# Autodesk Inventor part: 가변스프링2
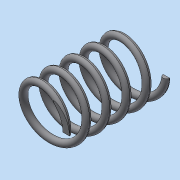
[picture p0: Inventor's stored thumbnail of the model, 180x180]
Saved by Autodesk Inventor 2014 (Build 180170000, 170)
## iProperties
Created: 2018-10
Part Number: 가변스프링2
Material: Generic
Document SubType Name: Modeling
Designer: kb542
Density: 1 g/cm^3
Appearance: Default
Mass: 0.778892 g
Surface Area: 15.8114 cm^2
Volume: 0.778892 cm^3
Author: kb542
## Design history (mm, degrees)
sketch "스케치1"
  geometry: L1 (0, 0)-(8, 0); L2 (8, 0)-(8, 30.472); L3 (8, 30.472)-(0, 30.472); L4 (0, 30.472)-(0, 0); C1 r 1 at (8, 0)
  constraints: 8 end point, 2 parallel, 1 centre point, 1 coincident, 1 horizontal, 1 perpendicular
  dimensions: "d0" = 30.47206 distance between parallel lines of L1 L3 (derived); "d1" = 2 diameter of C1; "d2" = 16 diameter of L2 L4
feature "코일1" sketch "스케치1" pitch "d3" = 10; turns "d5" = 5; dims "d4" = 30.47206 (= d0), "d6" = 0, angle "d7" = 90 deg, angle "d8" = 90 deg, "d9" = 0, "d10" = 0
sketch "스케치2"
  geometry: L1 (-7, 0)-(-9, 0) reference; 1 further point
  constraints: 1 horizontal alignment
extrude "돌출1" cut sketch "스케치2" distance "d11" = 10; taper "d12" = 0 deg
node "작업 평면1"
sketch "스케치3"
  geometry: L1 (-9, 0)-(-7, 0) reference; 1 further point
  constraints: 1 horizontal alignment
extrude "돌출2" cut sketch "스케치3" distance "d13" = 10; taper "d14" = 0 deg
node "솔리드1"
node "절단 모서리 투영1"
node "절단 모서리 투영2"
